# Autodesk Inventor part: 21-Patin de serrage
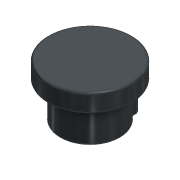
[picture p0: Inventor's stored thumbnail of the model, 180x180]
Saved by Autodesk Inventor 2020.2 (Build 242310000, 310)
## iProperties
Created: 2022-03
Part Number: 21-Patin de serrage
Material: Fonte, moulé
Document SubType Name: Modeling
Designer: %USERNAME%
Density: 7.15 g/cm^3
Appearance: Fonte grise
Author: %USERNAME%
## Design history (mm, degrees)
sketch "Esquisse2"
  geometry: L1 (0, 0)-(11.75, 0); L2 (11.75, 0)-(11.75, -5.2); L3 (11.75, -5.2)-(0, -5.2); L4 (0, -5.2)-(0, 0); L5 (0, -5.2)-(8.5, -5.2); L6 (8.5, -5.2)-(8.5, -15.2); L7 (8.5, -15.2)-(0, -15.2); L8 (0, -15.2)-(0, -5.2); L9 (0, 0)-(0, 7.646); 1 further point
  constraints: 18 end point, 4 parallel, 2 horizontal, 2 perpendicular, 1 vertical
  dimensions: "d0" = 23.5 diameter of L2 L9; "d1" = 17 diameter of L6 L9; "d2" = 5.2 distance of L1.end L2.end; "d3" = 15.2 distance between parallel lines of L1 L7
revolve "Révolution1" sketch "Esquisse2" stored, may be unused: angle "d4" = 90 deg
sketch "Esquisse3"
  geometry: C1 r 8.5 at (0, 0) reference; 2 further points
  constraints: 1 coincident
hole "Perçage1" sketch "Esquisse3" at (0, 0) diameter "d5" = 11; stored, may be unused: countersink angle "d9" = 90 deg, drill point angle "d11" = 0 deg; dims "d6" = 22, "d7" = 4, "d8" = 2, "d10" = 11
sketch "Esquisse4"
  geometry: L1 (5, -6.874)-(5, -8.66); L2 (-5, -6.874)-(-5, -8.66); A1 r 8.5 centre (0, 0) between (5, -6.874) and (-5, -6.874) reference; A2 r 10 centre (0, 0) between (5, -8.66) and (-5, -8.66); 1 further point
  constraints: 4 end point, 4 point on circle, 2 horizontal alignment, 1 centre point, 1 coincident, 1 parallel, 1 vertical
  dimensions: "d12" = 10 distance between parallel lines of L2 L1; "d13" = 20 diameter of A2
extrude "Extrusion1" join sketch "Esquisse4" stored distance "d14" = 10; taper "d15" = 0 deg
fillet "Congé1" dims "d16" = 1
node "Plan de construction1"
sketch "Esquisse5"
  geometry: 2 further points
  constraints: 1 vertical alignment
  dimensions: "d17" = 10 distance of point (0, 15.2) point (0, 5.2)
hole "Perçage2" sketch "Esquisse5" at (0, 5.2) diameter "d18" = 4.134; stored, may be unused: countersink angle "d22" = 90 deg, drill point angle "d24" = 0 deg; dims "d19" = 10, "d20" = 4, "d21" = 2, "d23" = 6
fillet "Congé2" dims "d25" = 0.5
node "Axe de construction1"
sketch "Esquisse6"
  geometry: L1 (-10, -16.45)-(-10, 16.45) reference; L2 (-7.5, -5.244)-(-7.5, -10.196); 1 further point
  constraints: 2 end point, 1 vertical
  dimensions: "d26" = 5 diameter of L2 L1
feature "SrfRévolution1" sketch "Esquisse6" dims angle "d27" = 270 deg
node "Solide1"
body "Srf1"
